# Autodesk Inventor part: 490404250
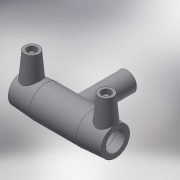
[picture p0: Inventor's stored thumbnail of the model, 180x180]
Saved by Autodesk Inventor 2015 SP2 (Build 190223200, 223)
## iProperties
Created: 2017-06
Part Number: 490404250
Material: Generic
Description: PLASSON TEE 250-250-250
Document SubType Name: Modeling
Designer: KIM
Mass: 57.3761 g
Surface Area: 241.06 cm^2
Volume: 57.3761 cm^3
Density: 1 g/cm^3
Appearance: Default
Author: KIM
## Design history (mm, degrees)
derived "490404.ipt"
feature "Solid1::490404.ipt"
tag "TaggingFeature1"
body "Solid1"
other parameters: "d0" = 538, "d2" = 326, "d3" = 129, "d4" = 134.5, "d5" = 293.4, "d6" = 237.5, "d8" = 168 deg, "d10" = 51.6, "d11" = 17.2, "d13" = 538, "d14" = 17.6296, "d17" = 225, "d19" = 3.52592, "d20" = 168 deg, "d22" = 303.18, "d23" = 326, "d24" = 294.0846, "d25" = 135 deg, "d26" = 376.6, "d27" = 135 deg, "d29" = 152, "d30" = 15, "d31" = 215.2, "d34" = 5 deg, "d35" = 15, "d39" = 5 deg, "d40" = 9.6, "d41" = 4.8, "d42" = 6, "d43" = 0, "d45" = 4, "d46" = 14, "d47" = 0, "d48" = -315, "d51" = 0, "d54" = 0, "d55" = 293.4, "d56" = 326, "d57" = 188.3, "d58" = 135 deg, "d59" = 129, "d60" = 129, "d61" = 135 deg, "d62" = 315, "d72" = 263.62, "d73" = 131.81, "d74" = -315, "d75" = 262.5, "d77" = 0, "d80" = 0, "d82" = 152, "d83" = 0, "d84" = 3, "d85" = 0, "d86" = 3, "d87" = 0, "d88" = 37.41, "d89" = 9.3525, "d90" = 37.41, "L_" = 538, "L_1" = 129, "D_" = 326, "A_" = 152, "d_2" = 12, "H_" = 315
